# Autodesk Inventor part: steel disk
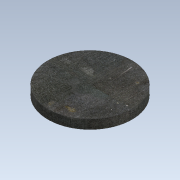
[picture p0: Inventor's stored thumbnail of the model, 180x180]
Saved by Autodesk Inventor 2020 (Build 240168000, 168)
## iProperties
Created: 2019-12
Part Number: steel disk
Material: Steel
Document SubType Name: Modeling
Designer: MPI
Density: 7.85 g/cm^3
Appearance: Plate
Author: MPI
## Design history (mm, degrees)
sketch "Sketch1"
  geometry: C1 r 76.2 at (0, 0); 1 further point
  constraints: 1 centre point, 1 coincident
  dimensions: "d0" = 152.4 diameter of C1
extrude "Extrusion1" new body sketch "Sketch1" distance "d1" = 16.51; taper "d2" = 0 deg
body "Solid1"
